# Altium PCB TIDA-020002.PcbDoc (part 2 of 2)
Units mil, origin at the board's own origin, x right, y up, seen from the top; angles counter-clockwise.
Board outline 1055.12 x 1877.5 mil, 6 copper layers (Layer 1 - Top Layer, Layer 2 - GND, Layer 3 - PWR, Layer 4 - Signal, Layer 5 - Signal/Gnd, Layer 6 - Bottom Layer), stack 62.2 mil thick; 103 components, 53 nets, 368 pads, 137 vias.
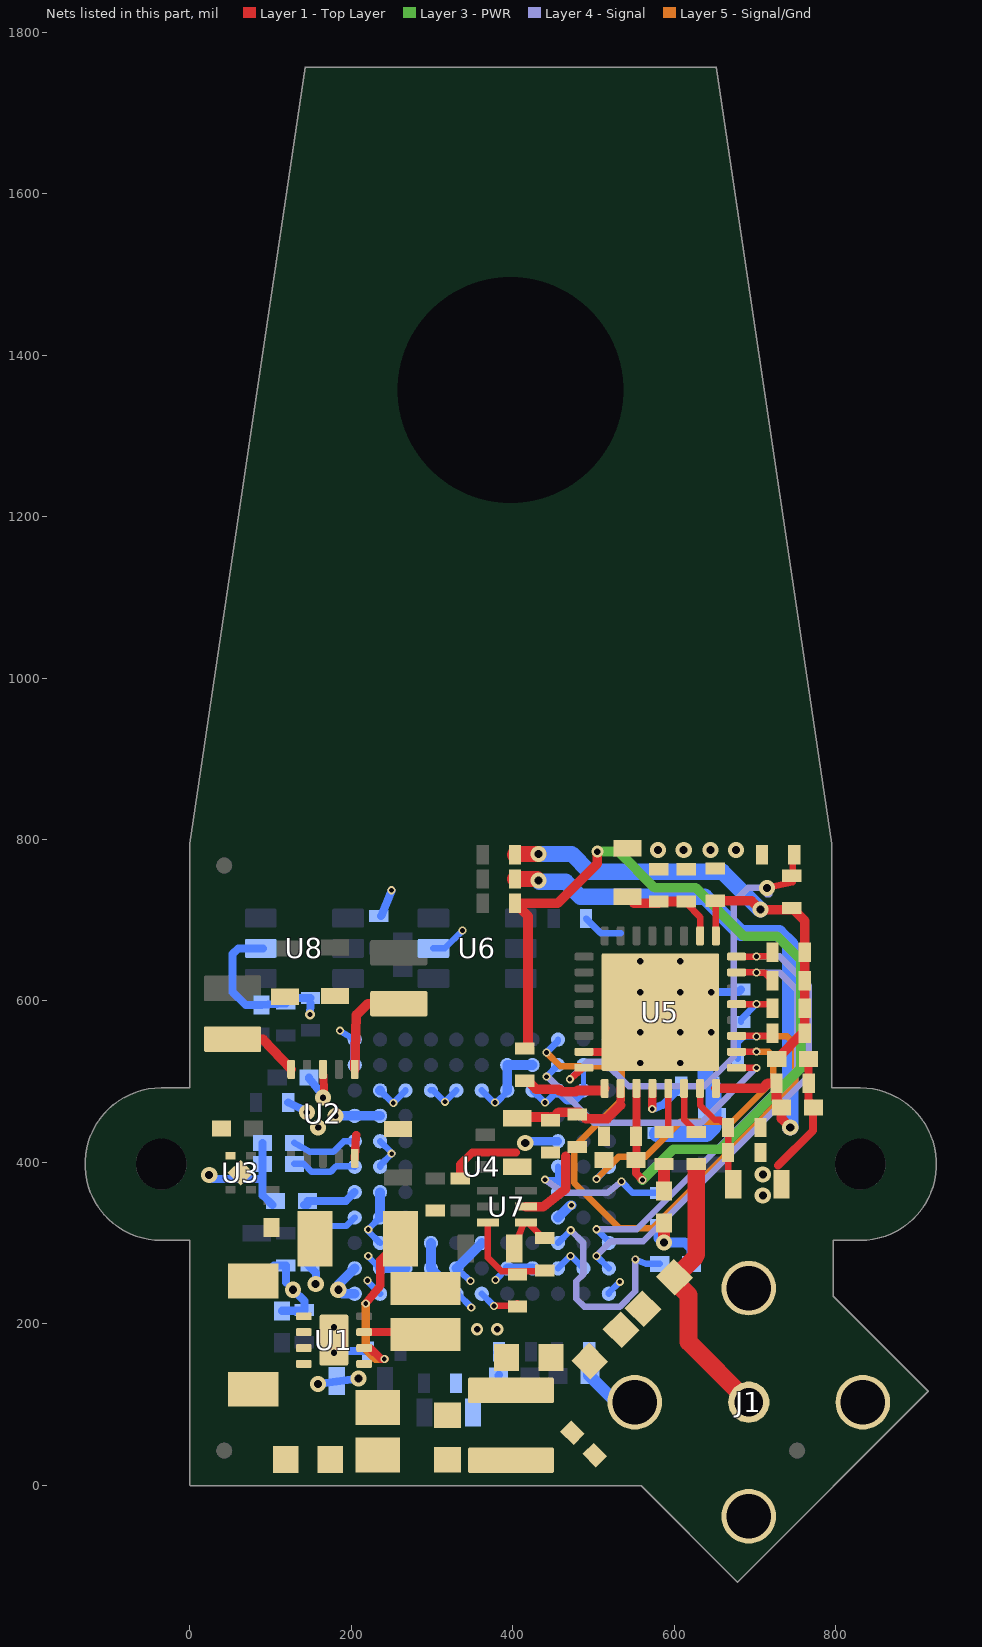
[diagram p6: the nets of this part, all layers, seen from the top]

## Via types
v1: diameter 10, hole 6, Layer 1 - Top Layer to Layer 6 - Bottom Layer, tented both sides, 88 vias
v2: diameter 20, hole 10, Layer 1 - Top Layer to Layer 6 - Bottom Layer, tented both sides, 26 vias
v3: diameter 19.68, hole 7.87, Layer 1 - Top Layer to Layer 6 - Bottom Layer, 10 vias
v4: diameter 19.68, hole 7.87, Layer 1 - Top Layer to Layer 6 - Bottom Layer, tented both sides, 6 vias
v5: diameter 15, hole 8, Layer 1 - Top Layer to Layer 6 - Bottom Layer, tented both sides, 6 vias
v6: diameter 12, hole 6, Layer 1 - Top Layer to Layer 6 - Bottom Layer, tented both sides, 1 vias

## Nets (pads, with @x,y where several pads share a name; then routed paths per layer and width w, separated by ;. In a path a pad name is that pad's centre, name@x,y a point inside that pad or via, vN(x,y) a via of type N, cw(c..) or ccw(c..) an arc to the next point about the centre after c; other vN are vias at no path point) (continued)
DOUTP_F: C40.1 J1.1 L2.1 | length 336.9
  Layer 1 - Top Layer w22: L2.1@598.44,255 625.64,281.64 ; L2.1@598.86,254.58 617.87,235.56 617.87,177.4 J1.1@692.64,102.64 ; 627.64,285.64 C40.1@627.64,393.64
FSIN: U4.L6 U5.18 | length 369.3
  Layer 1 - Top Layer w8: U5.18@677.49,536.79 v1@701.79,536.79
  Layer 5 - Signal/Gnd w8: v1(503.73,379) 531.73,407 565,407 608,450 672,450 723,501 723,531.29 717.29,537 v1(702,537)
  Layer 6 - Bottom Layer w8: v1@504,379.26 U4.L6@519.23,394.49
GND: C1.2 C2.2 C3.2 C4.2 C5.2 C6.2 C7.2 C8.2 C9.2 C10.2 C11.2 C12.2 C13.2 C14.2 C15.2 C16.2 C17.2 C18.2 C19.2 C20.2 C21.2 C22.2 C23.2 C24.2 C25.2 C26.2 C27.2 C28.2 C29.2 C30.2 C31.2 C32.2 C33.2 C34.2 C35.2 C36.2 C37.2 C38.2 C39.2 C41.2 C42.2 C44.2 C45.1 C46.2 C47.2 C48.1 C49.2 C50.2 C52.2 C53.1 C54.2 C55.2 C56.2 C57.2 C58.2 J1.2 J1.3 J1.4 J1.5 R11.1 R14.1 R15.1 R20.1 U1.1 U1.4 U1.5 U1.9 U2.5 U2.8 U3.2 U3.5 U4.A1 U4.A2 U4.A4 U4.A10 U4.A11 U4.B3 U4.B4 U4.B5 U4.B6 U4.B7 U4.B8 U4.B9 U4.B10 U4.B11 U4.C3 U4.C10 U4.D3 U4.D9 U4.D10 U4.E3 U4.E10 U4.E11 U4.F3 U4.F9 U4.F11 U4.G2 U4.G3 U4.G10 U4.H2 U4.H3 U4.H10 U4.J3 U4.J5 U4.J8 U4.J10 U4.K2 U4.K3 U4.K10 U4.L1 U4.L11 U5.7 U5.33@583,586 U6.2 U7.5 U8.2 | length 2773.5
  Layer 1 - Top Layer w8: v1(376.74,222) 403,222 R20.1@406,225
  Layer 1 - Top Layer w10: U2.8@165,515.12 v4@167,480 ; U2.5@204.37,404.88 206,434 206.37,433.63 ; C58.2@335,380 335,397 350,412 404,412 ; U5.7@488.51,536.79 533.79,536.79 U5.33@583,586 ; 729,396 772.45,439.45 772.45,470.97 766.69,476.73 C36.2@766.69,528
  Layer 1 - Top Layer w12: U7.5@416.62,345 438,345 466,367 466,407
  Layer 1 - Top Layer w15: v2@587.64,302.64 R11.1@587.64,324.95 R11.1@587.64,327.95
  Layer 6 - Bottom Layer w6: U4.K3@487.73,488.98 U4.K2@487.73,520.47
  Layer 6 - Bottom Layer w8: v1(186,563) U4.A1@204.27,551.97 ; U4.A1@201.92,554.31 U4.A1@205.69,554.31 ; v1@220.77,252 U4.B11@235.76,237.01 ; v1@221.14,314.62 U4.B9@235.76,300 ; v1@221.27,283 U4.B10@235.76,268.5 ; v1@221.27,317 U4.B8@235.76,331.5 ; U4.B6@235.76,394.49 235.76,396.02 250.75,411 U4.B5@235.76,425.98 ; U4.B3@235.76,488.98 251.74,473 267.26,488.52 U4.C3@267.26,488.98 ; U4.D3@298.76,488.98 301.75,488.98 316,474.72 U4.E3@330.25,488.98 ; U6.2@301.87,665 315.97,665 v1(337.91,686.94) ; U4.E11@330.25,237.01 331.99,237.01 v1@349,220 ; U4.E10@330.25,268.5 v1(348,253) ; U4.F11@361.75,237.01 v1@375.76,223 ; U4.F3@361.75,488.98 376.72,474 380,474 393.24,487.24 U4.G3@393.24,488.98 ; v1(378.74,254) U4.G10@393.24,268.5 ; U4.H3@424.74,488.98 v1@439.72,474 ; v1@441.26,474 U4.J3@456.24,488.98 ; U4.J10@456.24,268.5 471.73,284 472.24,284 U4.K10@487.73,268.5 ; C56.2@491,702 509,684 534,684 ; U4.L11@519.23,237.01 519.23,238.23 v1@532,251
  Layer 6 - Bottom Layer w10: v2@29,379 90.31,379 ; C14.2@86,252 86,253.5 104.5,272 C15.2@119,272 119,251 ; C28.2@90.31,424 C29.2@90.31,398 90.31,379 ; U8.2@90.87,665 60,665 53,658 53,611 69.31,594.69 C25.2@89,594.69 C26.2@119,597 125.5,603.5 C27.2@149.5,603.5 ; C30.2@102.31,347 90.31,359 90.31,379 ; C18.2@114,215.69 114,216 141,216 C19.2@142,217 142,228 v2(128,242) ; C11.2@122,474 v4@147,462 ; C35.2@147,272 156.27,262.73 v2@156.27,249.27 ; C10.2@147.69,505 147.69,503.92 v4@167,480 ; v6@149.5,583.5 v6(149,583) C27.2@149.5,597 ; v2(159,125) v2(209,132) ; v4@180.75,166 C17.2@221,166 ; C57.2@237,705 v1(250,737) ; C12.2@382.31,136 C12.2@383,136.69 ; v2@417.98,425.98 U4.J5@456.24,425.98 ; v3(645.99,610.8) 679.8,610.8 R15.1@683,614
  Layer 6 - Bottom Layer w12: v4@182.52,457.48 U4.A4@204.27,457.48 U4.B4@235.76,457.48 ; v2(184,242) v2@188.99,242 ; v2@184,248.24 U4.A10@204.27,268.5 ; v2@188.99,237.01 U4.A11@204.27,237.01 ; U4.A2@204.27,520.47 U4.A1@204.27,551.97 ; U4.B10@235.76,268.5 U4.C10@267.26,268.5 ; U4.B8@235.76,331.5 U4.B7@235.76,362.99 ; U4.D9@298.76,300 U4.D10@298.76,268.5 U4.E11@330.25,237.01 ; U4.E10@330.25,268.5 U4.F9@361.75,300 ; C13.2@382.31,164.31 C13.2@383,165 ; U4.G10@393.24,268.5 U4.H10@424.74,268.5 ; U4.G3@393.24,488.98 U4.G2@393.24,520.47 U4.H2@424.74,520.47 ; v2(415.64,423.64) v2@417.98,425.98 ; U4.J8@456.24,331.5 471.47,346.73 v1(473.13,346.73) ; U4.J3@456.24,488.98 467.59,477.62 476.37,477.62 U4.K3@487.73,488.98 ; v2(587.64,300.64) 613.36,300.64 621.69,292.31 C34.2@621.69,274
  Layer 6 - Bottom Layer w15: C32.2@495,165 495,135.69 C31.2@495.69,135 J1.3@528.05,102.64 ; v2@582,306.28 C33.2@582,322
  Layer 6 - Bottom Layer w20: C24.2@579,435 C23.2@609,435 640,435 649,444 C55.2@649,494 639,506 R14.1@639,528 v3@639,564
  other v1: 348.74,220 532.81,251.81 220.14,253.61 221.14,283.61 471.81,283.81 221.14,316.61 250.14,410.61 252.14,473.61 378.24,473.87 440,474 316.24,474.87
  other v2: 156,249 710,359 24,384 710,385 580,787 612,787 645,787 677,787
  other v3: 558.2,523.01 607.8,523.01 558.2,561.2 607.8,561.2 645.99,561.2 558.2,610.8 607.8,610.8 558.2,648.99 607.8,648.99
  other v4: 178.64,163.89 178.64,195.39 159,443 180.52,457.48 145,462 165,480
  other v5: 356,193 381,193
NetC1_1: C1.1 C2.1 L5.1 L6.1 R1.1
NetC4_1: C4.1 L1.2 R2.2 U1.6 | length 239.1
  Layer 1 - Top Layer w10: U1.6@216.04,169.8 223.46,169.8 237.26,156 v1(241,156) ; v1(218,225) 236,247 236,278.85 C4.1@260.15,303 ; C4.1@261.15,304 C4.1@260.15,303 ; C4.1@266.15,303 C4.1@260.15,303 ; L1.2@272.46,237 L1.2@287.64,252.18
  Layer 5 - Signal/Gnd w10: v1(218,225) 218,167.83 229.83,156 v1(241,156)
NetC28_1: C28.1 U4.A5 | length 82.9
  Layer 6 - Bottom Layer w8: C28.1@129.69,424 148.69,413 178,413 190.98,425.98 U4.A5@204.27,425.98
NetC29_1: C29.1 U4.A6 | length 81.8
  Layer 6 - Bottom Layer w8: C29.1@129.69,398 141,398 151,388 174.2,388 181.2,395 203.76,395 U4.A6@204.27,394.49
NetC30_1: C30.1 U4.A7 | length 67.1
  Layer 6 - Bottom Layer w10: C30.1@141.69,347 C30.1@145.69,347 ; C30.1@145.69,352 193.28,352 U4.A7@204.27,362.99
NetC33_1: C33.1 U4.J6 U4.J7 | length 204.5
  Layer 4 - Signal w8: v1(440.15,378.39) 463,362 517.19,362 v1(535,376)
  Layer 6 - Bottom Layer w8: v1@441,378 456.24,378 ; U4.J7@456.24,362.99 456.24,378 ; U4.J6@456.24,394.49 456.24,378 ; v1(535,376) 549,362 C33.1@582,362
NetC34_1: C34.1 U4.J9 | length 272.2
  Layer 4 - Signal w8: v1(472,315.71) 487.73,299.97 487.73,261.27 479,252.54 479,231 489,221 533,221 552,240 v1(552,279.71)
  Layer 6 - Bottom Layer w8: U4.J9@456.24,300 v1@471.24,315 ; v1(552,279.71) 566,274 C34.1@582.31,274
NetC35_1: C35.1 U4.A8 | length 65.6
  Layer 6 - Bottom Layer w8: C35.1@147,312 156.27,321.27 156.54,321 193.77,321 U4.A8@204.27,331.5
NetC40_2: C40.2 U5.14 | length 63.1
  Layer 1 - Top Layer w8: U5.14@612.53,491.51 612.53,452.75 C40.2@627.64,437.64 C40.2@624.64,437.64
NetC43_1: C43.1 R11.2 | length 30.3
  Layer 1 - Top Layer w15: R11.2@587.64,367.32 C43.1@587.64,397.64
NetC43_2: C43.2 U5.13 | length 56
  Layer 1 - Top Layer w8: C43.2@587.64,437.64 592.84,442.84 U5.13@592.84,491.51
NetC50_1: C50.1 R10.1 U5.8 | length 572.9
  Layer 1 - Top Layer w8: v1(470.85,502.87) U5.8@488.51,517.1 ; v2(715,740) 747,747 747,779 C50.1@749,781
  Layer 4 - Signal w8: v1(470.85,502.87) 492.32,524.34 513.67,524.34 544,494 637.35,494 674,530.65 674,722 692,740 v2(715,740) ; v2@715,732 v2@718,732
NetC51_2: C51.2 U5.9 | length 101.7
  Layer 1 - Top Layer w12: C51.2@419,500.47 429,490.47 457.53,490.47 ; 457.53,489 459,489 460.75,487.25 479.03,487.25 480.78,489 511.59,489 U5.9@514.1,491.51
NetC55_1: C55.1 U5.12 | length 72
  Layer 1 - Top Layer w10: v1(573,466) U5.12@573.16,491.51
  Layer 6 - Bottom Layer w10: v1(573,466) 586,471 C55.1@609,494
NetL1_1: L1.1 U1.7 | length 73.9
  Layer 1 - Top Layer w10: U1.7@216.04,189.48 282.02,189.48 L1.1@287.64,195.09
NetL2_2: L2.2 L3.1
NetL3_2: L3.2 L4.1
NetL4_2: L4.2 L5.2 R1.2
NetL7_1: L7.1 U2.6 | length 125.8
  Layer 1 - Top Layer w12: U2.6@204.37,515.12 206.37,582.37 220.5,596.5 L7.1@259,596.5
NetL8_1: L8.1 U2.10 | length 89.2
  Layer 1 - Top Layer w12: L8.1@53,552.5 91.09,552.5 91.09,551.66 U2.10@125.63,515.12
NetR13_1: R13.1 R15.2 U5.21 | length 76.5
  Layer 1 - Top Layer w8: U5.21@677.49,595.84 701.84,595.84 v1(702,596) 717,596 R13.1@722,591
  Layer 6 - Bottom Layer w8: R15.2@683,574 683,577 v1(702,596)
NetR17_1: R17.1 R19.2 U7.4 | length 67.4
  Layer 1 - Top Layer w8: R17.1@402,294 412,320.69 U7.4@416.62,325.32 418.88,325.32 R19.2@440.2,304
NetR19_1: R19.1 R20.2 U7.3 | length 118.5
  Layer 1 - Top Layer w8: U7.3@369.38,325.32 369.38,281.75 386.12,265 406,265 436,265 R19.1@437,266
SCL: R8.1 U4.L10 U5.24 | length 615.4
  Layer 1 - Top Layer w8: U5.24@677.49,654.9 v1@701.9,654.9 ; v1(702,655) 717,655 R8.1@722,660
  Layer 4 - Signal w8: v1(504,284) 522,302 561.69,302 767,507.31 767,619 731,655 v1(702,655)
  Layer 6 - Bottom Layer w8: v1(504,284) 504,283.73 U4.L10@519.23,268.5
SDA: R9.1 U4.L9 U5.23 | length 557
  Layer 1 - Top Layer w8: U5.23@677.49,635.21 v1@701.79,635.21 ; v1(702,635) 712,635 R9.1@722,625
  Layer 4 - Signal w8: v1(504,317) 553.84,317 752.73,515.89 ; v1(702,635) 730.81,635 752.73,613.09 752.73,518.7
  Layer 6 - Bottom Layer w8: v1(504,317) 519.23,301.77 U4.L9@519.23,300
SYS_CLEAR: U4.J2 U5.17 | length 356.3
  Layer 1 - Top Layer w8: U5.17@677.49,517.1 v1@701.9,517.1
  Layer 4 - Signal w8: v1@442.58,506.99 500.57,449 634,449 v1(702,517)
  Layer 6 - Bottom Layer w8: v1(442,506) U4.J2@456.24,520.47
VCC_PLL: C38.1 C39.1 C51.1 L10.2 U5.11 | length 1137.3
  Layer 1 - Top Layer w10: U5.11@553.47,491.51 553.47,403.79 C38.1@552.69,403 552.69,386.32 v1(561,378)
  Layer 1 - Top Layer w12: C51.1@419,540.47 419,705 L10.2@403,721 456,721 505,770 v5(505,785)
  Layer 3 - PWR w12: v5(505,785) 531,785 576,740 627,740 687,680 728,680 756.93,651.07 756.93,515.93 657,416 599,416 v1(561,378)
VCC_POC: C3.1 L6.2 U1.2 U1.3
VDD1: C36.1 C37.1 L9.2 R8.2 R9.2 R10.2 R12.2 R13.2 U5.25 | length 679.1
  Layer 1 - Top Layer w8: C37.1@651,721 651.9,720.1 U5.25@651.9,680.49
  Layer 1 - Top Layer w12: C37.1@651,724 696,724 v2(707,713) 744,713 R10.2@746,715 762,699 R8.2@762,660 ; C36.1@727.31,528 759.31,560 R12.2@762,560 R13.2@762,591 R9.2@762,625 R8.2@762,655.28
  Layer 1 - Top Layer w20: L9.2@403,781 404,782 v2(432,782)
  Layer 6 - Bottom Layer w20: v2(432,782) 473,782 495,760 660,760 v2(707,713)
VDD1_CAP: C44.1 C45.2 C46.1 U5.26 | length 124.4
  Layer 1 - Top Layer w8: C44.1@581,721 C44.1@583,723 ; C46.1@615,721 632.21,703.79 U5.26@632.21,680.49
  Layer 1 - Top Layer w12: C45.2@542.39,729 550.39,721 C44.1@581,721 ; C44.1@583,723 C46.1@615,723
VDDDRV: C41.1 C42.1 L11.2 U5.16 | length 738.7
  Layer 1 - Top Layer w12: U5.16@651.9,491.51 709.51,491.51 716,498 C42.1@727,498 727,477.05 733.08,470.97 733.08,453.92 v2(744,443)
  Layer 1 - Top Layer w20: L11.2@403,751 v2@430,751
  Layer 6 - Bottom Layer w20: v2(432,749) 433.5,747.5 465.8,747.5 474,739.3 474,739 484,729 638,729 683,684 730,684 744,670 v2(744,443)
VDDDRV_CAP: C47.1 C48.2 C49.1 U5.15 | length 140
  Layer 1 - Top Layer w8: U5.15@632.21,491.51 632.21,470.79 650.5,452.5 657.5,452.5 C49.1@667,443 C47.1@667,412 667,379.02 C48.2@673.39,372.64
VDDPLL_CAP: C52.1 C53.2 C54.1 U5.10 | length 156.9
  Layer 1 - Top Layer w10: 533.79,470.79 U5.10@533.79,491.51
  Layer 1 - Top Layer w12: C53.2@412,456 C52.1@444,456 ; C52.1@447,452 C52.1@451,456 ; C52.1@448,456 C52.1@451,456 ; 533.79,470.79 517,454 491,454 483,462 468.5,462 457,462 C52.1@451,456
XCLK: R12.1 R14.2 U4.J1 U5.19 | length 852.5
  Layer 1 - Top Layer w8: U5.19@677.49,556.47 718.47,556.47 R12.1@722,560
  Layer 5 - Signal/Gnd w8: v1(442,536) 459,519 528,519 535.05,511.95 535.05,477.68 476.36,419 476.36,374.36 532.72,318 573,318 750,495 750,546 740,556 v1(702,556)
  Layer 6 - Bottom Layer w8: v1(442,536) 456.24,550.24 U4.J1@456.24,551.97 ; R14.2@679,528 679,548 687,556 v1(702,556)
pads on no net: FID1.1 FID2.1 FID3.1 FID4.1 FID5.1 FID6.1 LH1.MT1 LH1.MT2 U1.8 U2.11 U4.A9 U4.F10 U4.G11 U4.K4 U4.K5 U4.K6 U4.K7 U4.K8 U4.K9 U4.L5 U4.L8 U5.20 U5.22 U5.33@533.39,536.39 U5.33@533.39,586 U5.33@533.39,635.61 U5.33@583,536.39 U5.33@583,586 U5.33@583,635.61 U5.33@632.61,536.39 U5.33@632.61,586 U5.33@632.61,635.61

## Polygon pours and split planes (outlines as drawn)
GND on Layer 2 - GND "Layer 2 - GND - GND" (solid, remove dead copper, pour order 16): 677.64,-142.36 -132.36,-142.36 -132.36,799.64 917.64,799.64 917.64,-142.36
GND on Layer 3 - PWR "Layer 5 - PWR - GND" (solid, remove dead copper, pour order 10): 677.64,-142.36 -132.36,-142.36 -132.36,799.64 917.64,799.64 917.64,-142.36
GND on Layer 4 - Signal "Layer 4 - Signal - GND" (solid, remove dead copper, pour order 14): 677.35,-141.09 -132.65,-141.09 -132.65,800.91 917.35,800.91 917.35,-141.09
GND on Layer 5 - Signal/Gnd "Layer 3 - Signal - GND" (solid, remove dead copper, pour order 12): 677.64,-142.36 -132.36,-142.36 -132.36,799.64 917.64,799.64 917.64,-142.36
1V8 on Layer 1 - Top Layer "1V8_L01_P018" (solid, remove dead copper, pour order 18): 20,678 20,796.99 19.99,797 371,797 371,709 372,708 366.4,702.4 301.87,702.4 301.87,731.13 301,732 137,732 137,670 135,672 20,672 20,678

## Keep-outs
Keep-Out Layer:
  lines w10: -35.48,298.15 ccw(c-35.43,303.15) -35.43,298.15 ; -35.48,298.15 cw(c-35.43,397.64) -35.48,497.13 ; -35.48,298.15 ccw(c-35.43,397.64) -35.43,298.15 ; -35.48,497.13 cw(c-35.43,397.64) -35.43,497.13 ; -35.48,497.13 cw(c-35.43,492.13) -35.43,497.13 ; -35.48,497.13 cw(c-35.43,492.13) -35.43,497.13 ; -35.43,298.15 -5,298.15 -5,0 ; -35.43,497.13 -5,497.13 -5,794.57 ; -5,0 ccw(c0,0) -3.54,-3.54 -3.52,-3.55 ; -5,0 ccw(c0,0) -3.52,-3.55 ; -5,794.57 cw(c0,794.64) -5,794.64 ; -5,794.57 cw(c0,794.64) -5,794.64 ; -5,794.57 -5,794.71 ; -5,794.64 cw(c0,794.64) -5,794.71 ; -5,794.64 -5,795.28 ; -5,794.71 -5,795.28 ; -5,795.28 cw(c0,795.28) -4.71,796.95 ; -5,795.28 ccw(c0,795.28) -5,795.28 ; -5,795.28 cw(c0,795.28) -4.71,796.95 ; -4.71,796.95 137.94,1757.87 ; -3.52,-3.55 -2.56,-4.51 ; -2.56,-4.51 ccw(c0.99,-0.99) 0.99,-5.99 ; -2.54,-4.53 ccw(c0.99,-0.99) 0.99,-5.99 ; -2.56,-4.51 -2.54,-4.53 ; 0.99,-5.99 557.2,-5.99 675.08,-123.88 ; 137.94,1757.87 cw(c142.89,1757.14) 142.89,1762.14 ; 137.94,1757.87 cw(c142.89,1757.14) 142.89,1762.14 ; 142.89,1762.14 652.39,1762.14 ; 652.39,1762.14 cw(c652.39,1757.14) 657.33,1757.87 ; 652.39,1762.14 cw(c652.39,1757.14) 657.33,1757.87 ; 657.33,1757.87 799.99,796.95 ; 675.08,-123.88 ccw(c678.64,-120.36) 682.17,-123.9 682.19,-123.88 ; 675.08,-123.88 675.1,-123.9 ccw(c678.64,-120.36) 682.19,-123.88 ; 682.19,-123.88 918.66,112.58 ; 799.99,796.95 cw(c795.28,795.28) 800.28,795.28 ; 799.99,796.95 cw(c795.28,795.28) 800.28,795.28 ; 800.28,794.55 ccw(c795.28,794.64) 800.28,794.64 ; 800.28,794.55 ccw(c795.28,794.64) 800.28,794.64 ; 800.28,794.55 800.28,497.13 830.71,497.13 ; 800.28,794.55 800.28,794.73 ; 800.28,794.64 ccw(c795.28,794.64) 800.28,794.64 ; 800.28,794.64 ccw(c795.28,794.64) 800.28,794.64 ; 800.28,794.64 ccw(c795.28,794.64) 800.28,794.73 ; 800.28,794.64 800.28,795.28 ; 800.28,794.73 800.28,795.28 ; 800.28,795.28 ccw(c795.28,795.28) 800.28,795.28 ; 830.71,298.15 ccw(c830.71,303.15) 830.71,298.15 ; 830.71,298.15 ccw(c830.71,303.15) 830.75,298.15 ; 830.71,298.15 ccw(c830.71,303.15) 830.75,298.15 ; 830.71,298.15 ccw(c830.71,397.64) 830.75,298.15 ; 830.71,298.15 802.27,298.15 802.27,236.08 918.66,119.69 ; 830.71,497.13 cw(c830.71,492.13) 830.75,497.13 ; 830.71,497.13 ccw(c830.71,492.13) 830.71,497.13 ; 830.71,497.13 cw(c830.71,397.64) 830.75,497.13 ; 830.71,497.13 cw(c830.71,492.13) 830.75,497.13 ; 830.75,298.15 ccw(c830.71,397.64) 930.2,397.64 ccw(c830.71,397.64) 830.75,497.13 ; 918.66,112.58 ccw(c915.14,116.14) 920.14,116.14 ; 918.66,112.58 918.67,112.6 ccw(c915.14,116.14) 920.14,116.14 ; 918.66,119.69 cw(c915.14,116.14) 920.14,116.14 ; 918.66,119.69 918.67,119.67 cw(c915.14,116.14) 920.14,116.14
  text ".Layer_Name" at 444.64,-860.86 h60

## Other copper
Layer 1 - Top Layer:
  region net NetC4_1: 269,336 280,336 291,347 315,347 315,330 312,330 289,330 289,328 289,266.82 335.12,266.82 334.88,223 244.64,223 244.64,336
  region net GND: 570,750 561,759 523.78,759 522.64,760.14 522.64,799 717,799 717,758.64 708.64,758.64 700.64,752.27 700.64,750
  region net GND: 699,450 699,347.64 743.64,347.64 743.64,391.64 717,418.28 717,455.64 704.64,455.64
  region net NetL2_2: 505.14,189.14 530.64,163.64 581.14,214.14 555.64,239.64
  region net GND: 483.64,37.64 512.64,66.64 512.64,106.64 512.64,118.64 533.64,139.64 565.64,139.64 591.64,113.64 591.64,87.64 562.64,58.64 552.76,58.64 507.2,13.08 483.64,36.64
  region net GND: 128.37,315.37 149,336 196,336 195.91,279.64 196.64,192.64 196.92,158.27 196.92,154 224.64,154 224.64,142.63 247.63,119.64 262.64,119.64 262.64,74.64 159.64,74.64 159.64,108.08 132,138.89 132,154 152.49,154 159.64,158.55 159.64,204 59.28,204 45,218.27 45,321 45,330 103.35,330 117.98,315.37
  region net NetC1_1: 436.64,45.64 442,51 472,81 490,63 457,30 457,14.64 157.64,14.64 157.64,49.64 169.64,49.64 178.64,58.64 259.64,58.64 272.64,45.64
  region net VCC_POC: 135.64,69.64 112.64,92.64 112.64,159.27 119.01,165.64 151.64,165.64 151.64,193.64 150.64,194.64 109.64,194.64 44,129 44,95.64 54.64,95.64 101.64,48.64 102.64,48.64 102.64,13.64 103.64,14.64 135.64,14.64
  region net NetL3_2: 434,173 434,143 433,142 478,142 493,127 515,149 491,173
  region net NetL4_2: 378,143 368,133 333,133 304,104 304,74 337,74 366,103 451,103 450,104 450,133 420,133 409,144 409,175 379,175 378,175
  region net 3V3: 226,349 249,372 316,372 316,386 231,386 215,370 177,370 172,375 172,417 141,417 142.93,368.08 69.35,367.69 67.4,365.74 59.26,365.74 56,369 43.46,369 43.46,349
  region net 1V8: 138,678 138,651 84,651 84,601 20,601 20,678
  region net 1V2: 295,725 160.42,725 142.89,725 142.89,682 160.42,682 160.42,642.5 295,642.5
  region net GND: 56,381 63,374 67,374 78.5,385.5 56.27,407.73 56.27,452.16 27.16,452.16 27,396 17,386 17,381 18,376 21.77,372.23 24,372 29,372 38,381
  region net GND: 491,428 506,443 507,442 524,442 524,390 395,390 395,428
  region net GND: 132,594.69 160,559.51 160,514 171,514 172,557 194,557 194,576.5 194,615.85 102,615.85 102,594.68
  text ".Layer_Name" at 444.64,-860.86 h60
Layer 2 - GND:
  pour cut-out: 336,15 335,16 335,144 468,144 467,143 467,16 338,16 336,14
  text ".Layer_Name" at 444.64,-860.86 h60
Layer 3 - PWR:
  region net 1V2: 15.39,402.8 34.2,402.8 42,395 42,375.07 15.39,353.97 15.39,12 110.91,12 491,12 494,15 494,119 257,119 257,82 65,82 65,680.51 179.06,680.51 179.06,725 15.39,725 15.39,573.61
  region net 2V9: 96,90 96,521 70.27,521 70.27,90
  text ".Layer_Name" at 444.64,-860.86 h60
Layer 5 - Signal/Gnd:
  text ".Layer_Name" at 444.64,-860.86 h60
Layer 4 - Signal:
  text ".Layer_Name" at 444.64,-860.86 h60
Layer 6 - Bottom Layer:
  region net GND: 524,687 524,578.05 511,559 511,544 659,544 659,618 590,687
  region net GND: 394.5,206 394.5,75 324,75 324,206
  text ".Layer_Name" at 444.64,-860.86 h60

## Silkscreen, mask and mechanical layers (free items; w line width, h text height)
Top Overlay:
  text "TIDA-020002" at 223,552 h40
  text ".Layer_Name" at 444.64,-860.86 h60
Bottom Overlay:
  lines w6: 165.9,553 165.9,565.9
  lines w10: 61.64,732.64 63,332 ; 62.64,732.64 732.64,732.64 732.64,62.64 62.64,62.64 63,234
  text ".Layer_Name" at 444.64,-860.86 h60
Top Paste:
  text ".Layer_Name" at 444.64,-860.86 h60
Bottom Paste:
  text ".Layer_Name" at 444.64,-860.86 h60
Top Solder:
  text ".Layer_Name" at 444.64,-860.86 h60
  text ".Layer_Name" at 444.64,-860.86 h60
Bottom Solder:
  text ".Layer_Name" at 444.64,-860.86 h60
Drill Guide:
  text ".Layer_Name" at 444.64,-860.86 h60
M1 Board Outline:
  lines w10: 0,0 0,303.15 -35.43,303.15 cw(c-35.43,397.64) -35.43,492.13 0,492.13 0,795.28 ; 0,794.64 142.89,1757.14 652.39,1757.14 795.28,794.64 ; 0.99,-0.99 559.27,-0.99 678.64,-120.36 915.14,116.14 797.27,234.01 797.27,303.15 830.71,303.15 ccw(c830.71,397.64) 830.71,492.13 795.28,492.13 795.28,795.28 ; 4.64,819.64 31.64,819.64 ; 63.64,819.64 95.28,819.64 ; 127.28,819.64 158.91,819.64 ; 190.91,819.64 222.55,819.64 ; 254.55,819.64 286.19,819.64 ; 318.19,819.64 349.83,819.64 ; 381.83,819.64 413.46,819.64 ; 387.64,780.64 404.64,780.64 ; 397.64,732.64 397.64,772.64 ; 445.46,819.64 477.1,819.64 ; 509.1,819.64 540.74,819.64 ; 572.74,819.64 604.38,819.64 ; 636.38,819.64 668.02,819.64 ; 700.02,819.64 731.65,819.64 ; 763.65,819.64 790.64,819.64 ; 377.64,772.64 417.64,772.64 397.64,792.64 377.64,772.64
  text "V-SCORE" at 237.64,663.64 h75
  text ".Layer_Name" at 444.64,-860.86 h60
M2 Board Dimensions:
  rectangle: -7.86,-412.86 367.14,-287.86
  rectangle: -132.86,-287.86 -7.86,-162.86
  lines w7: -132.86,-287.86 867.14,-287.86 ; -7.86,-412.86 -7.86,-162.86 ; 117.14,-412.86 117.14,-162.86 ; 367.14,-412.86 367.14,-162.86 ; 617.14,-412.86 617.14,-162.86 ; -132.86,-412.86 -132.86,-162.86 867.14,-162.86 867.14,-412.86 -132.86,-412.86
  lines w10: -172.36,397.64 397.64,397.64 ; -132.86,-477.86 -132.86,-457.86 ; -72.86,-487.86 -132.86,-467.86 ; -72.86,-447.86 -132.86,-467.86 ; 91.22,-467.86 -132.86,-467.86 ; 397.64,-172.36 397.64,397.64 ; 397.64,967.64 397.64,397.64 ; 643.05,-467.86 867.14,-467.86 ; 807.14,-487.86 867.14,-467.86 ; 807.14,-447.86 867.14,-467.86 ; 867.14,-477.86 867.14,-457.86 ; 967.64,397.64 397.64,397.64
  text "1000 (mil)" at 101.22,-503.85 h60
  text ".Layer_Name" at 444.64,-860.86 h60
M3 3D STEP Top:
  text ".Layer_Name" at 444.64,-860.86 h60
M4 3D STEP Bottom:
  text ".Layer_Name" at 444.64,-860.86 h60
M5 Assembly Top:
  lines w10: -424.36,-932.53 6175.64,-932.53 ; -424.36,-729.2 6177.64,-729.2 ; -424.36,-525.86 -424.36,-1135.86 3580.64,-1135.86 6177.64,-1135.86 6177.64,-525.86 -423.86,-525.86 -423.86,-1135.86 1151.64,-1135.86 ; 2040.64,-1135.86 2040.64,-525.86 ; 3307.64,-729.2 3307.64,-525.86 ; 4147.64,-729.2 4147.64,-525.86 ; 4769.64,-1142.36 4769.64,-939.53
  text "COMPONENTS MARKED 'DNP' SHOULD NOT BE POPULATED." at 1021.14,-320.86 h60
  text "ASSEMBLY VARIANT:" at 1020.64,-436.36 h60
  text ".VariantName" at 2056.64,-436.36 h60
  text "PCB VIEWED FROM TOP SIDE" at -360.86,-658.03 h60
  text "BOARD #:" at 2115.64,-658.03 h60
  text ".PRJ_Number" at 2661.14,-658.03 h60
  text "REV:" at 3505.64,-658.03 h60
  text ".PCB_Rev" at 3797.14,-658.03 h60
  text "SVN REV:" at 4343.64,-658.03 h60
  text ".VersionControl_RevNumber" at 4849.64,-658.03 h60
  text "IGNORE ->" at -360.86,-860.86 h60
  text "PLOT NAME =" at -360.86,-1066.7 h60
  text ".plot_File_Name" at 444.64,-1066.7 h60
  text "GENERATED    :" at 2117.64,-1066.7 h60
  text ".Print_Date" at 2987.14,-1066.7 h60
  text ".Print_Time" at 3716.14,-1066.7 h60
  text "TEXAS INSTRUMENTS" at 4980.64,-1066.7 h60
M6 Assembly Bottom:
  lines w10: -424.86,-729.7 6177.14,-729.7 ; -422.86,-933.03 6177.14,-933.03 ; 983.14,-1142.86 983.14,-940.03 ; 1605.14,-729.7 1605.14,-526.36 ; 2445.14,-729.7 2445.14,-526.36 ; 3712.14,-1136.36 3712.14,-526.36 ; 4601.14,-1136.36 6176.64,-1136.36 6176.64,-526.36 -424.86,-526.36 -424.86,-1136.36 2172.14,-1136.36 6177.14,-1136.36 6177.14,-526.36
  text "COMPONENTS MARKED 'DNP' SHOULD NOT BE POPULATED." at 5969.64,-320.36 h60
  text ".VariantName" at 4925.64,-436.36 h60
  text "ASSEMBLY VARIANT:" at 5964.64,-436.36 h60
  text ".VersionControl_RevNumber" at 903.14,-658.53 h60
  text "SVN REV:" at 1409.14,-658.53 h60
  text ".PCB_Rev" at 1955.64,-658.53 h60
  text "REV:" at 2247.14,-658.53 h60
  text ".PRJ_Number" at 3091.64,-658.53 h60
  text "BOARD #:" at 3637.14,-658.53 h60
  text "PCB VIEWED FROM BOTTOM SIDE" at 6113.64,-658.53 h60
  text "IGNORE ->" at 2415.49,-860.86 h60
  text "TEXAS INSTRUMENTS" at 772.14,-1067.2 h60
  text ".Print_Time" at 2036.64,-1067.2 h60
  text ".Print_Date" at 2765.64,-1067.2 h60
  text "GENERATED    :" at 3635.14,-1067.2 h60
  text ".plot_File_Name" at 5308.14,-1067.2 h60
  text "PLOT NAME =" at 6113.64,-1067.2 h60
M9 Title Sheet:
  drawing of 1178 lines, arcs and shapes, not listed
  text "1" at 607.48,8034.14 h70
  text "2" at 3103.14,8034.14 h70
  text "3" at 5592.48,8034.14 h70
  text "4" at 8099.15,8034.14 h70
  text "5" at 10598.14,8034.14 h70
  text "6" at 13103.14,8034.14 h70
  text "A" at -548.86,6891.14 h70
  text "A" at 14251.14,6891.14 h70
  text "B" at -548.86,4511.14 h70
  text "B" at 14251.14,4511.14 h70
  text "C" at -548.86,2136.14 h70
  text "C" at 14251.14,2136.14 h70
  text "PROJECT TITLE:" at 11211.14,275.14 h45
  text ".PRJ_Title" at 11261.14,141.81 h70
  text "DESIGNED FOR:" at 11211.14,-25.86 h45
  text ".PRJ_Customer" at 11261.14,-165.86 h70
  text "D" at -548.86,-233.86 h70
  text "D" at 14251.14,-233.86 h70
  text "FILE NAME:" at 11211.14,-325.86 h45
  text ".PCB_File_Name_No_Path" at 11261.14,-445.86 h70
  text "Texas Instruments (TI) and/or its licensors do not warrant the accuracy or completeness of this specification" at 6241.64,-607.7 h45
  text "ENGINEER:" at 11211.14,-615.86 h45
  text "LAYOUT BY:" at 12716.14,-615.86 h45
  text "or any information contained therein. TI and/or its licensors do not warrant that this design will meet" at 6196.65,-720.37 h45
  text ".PRJ_Engineer" at 11261.14,-770.85 h70
  text "JMM" at 12719.64,-802.36 h100
  text "s  o  l  u  t  i  o  n  s" at 13577.64,-805.36 h68
  text "the specifications, will be suitable for your application or fit for any particular purpose, or will operate in" at 6196.65,-833.03 h45
  text ".Layer_Name" at 444.64,-860.86 h60
  text "ALTIUM DESIGNER VERSION:" at 12716.14,-925.86 h45
  text "an implementation. TI and/or its licensors do not warrant that the design is production worthy. You should" at 6196.65,-945.7 h45
  text "completely validate and test your design implementation to confirm the system functionality for your application." at 6241.64,-1058.36 h45
  text ".print_Scale" at 11261.14,-1059.19 h70
  text ".Application_BuildNumber" at 12766.64,-1059.19 h70
  text "1" at 607.48,-1265.86 h70
  text "2" at 3103.14,-1265.86 h70
  text "3" at 5592.48,-1265.86 h70
  text "4" at 8099.15,-1265.86 h70
  text "5" at 10598.14,-1265.86 h70
  text "6" at 13103.14,-1265.86 h70
M10 Fab Notes:
  drawing of 212 lines, arcs and shapes, not listed
  text "DESIGN INFORMATION" at 12248.66,6807.64 h60
  text "(REFER ALSO ARRAY/PANEL PROFILING INFORMATION)" at 11887.1,6645.92 h60
  text "BOARD SIZE" at 11201.1,6641.64 h60
  text "795.28MIL" at 11663.42,6513.82 h60
  text "X" at 12169.1,6513.82 h60
  text "795.28MIL" at 12400.42,6513.82 h60
  text "Number of Layers :" at 11604.1,6316.64 h60
  text "6" at 12698.91,6306.64 h60
  text "MIN. TRACK WIDTH:" at 11604.1,6177.64 h60
  text "5" at 12700.34,6177.64 h60
  text "MIL" at 12855.1,6177.64 h60
  text "MIN. CLEARANCE:" at 11604.1,6045.64 h60
  text "4" at 12700.34,6045.64 h60
  text "MIL" at 12855.1,6045.64 h60
  text "MIN. VIA PAD SIZE:" at 11604.1,5913.64 h60
  text "10" at 12670.35,5913.64 h60
  text "MIL" at 12855.1,5913.64 h60
  text "0.05mm (2MIL)" at 12299.1,5771.93 h60
  text "MINIMUM ANNULAR RING" at 11274.87,5767.64 h60
  text "EXTERNAL" at 13007.1,5767.64 h60
  text "PER" at 11474.87,5649.64 h60
  text "IPC-D-275 CLASS 2 LEVEL C" at 11694.87,5649.64 h60
  text "MIL, HOLES" at 13183.1,5537.35 h60
  text "+/-" at 12790.64,5536.64 h60
  text "+/-" at 13644.64,5536.64 h60
  text "REGISTRATION TOLERANCES:" at 11274.87,5531.64 h60
  text "METAL" at 12474.64,5531.64 h60
  text "5" at 13050.84,5531.64 h60
  text "3" at 13883.84,5531.64 h60
  text "MIL" at 14000.1,5531.64 h60
  text "MATERIAL:" at 11200.1,5322.18 h60
  text "FR-4 High Tg" at 12186.54,5181.85 h60
  text "FR-408" at 11621.1,5173.28 h60
  text "X" at 12033.1,5173.28 h60
  text "OTHER" at 13109.1,5173.28 h60
  text "62 MIL (1.6mm) +/-10%" at 11941.2,5010.56 h60
  text "THICKNESS:" at 11274.87,5006.28 h60
  text "X" at 11813.04,5006.28 h60
  text "OTHER" at 13226.1,5006.28 h60
  text "TOLERANCE:" at 11274.87,4848.28 h60
  text "X" at 12114.17,4848.28 h60
  text "ANSI IPC-6012 TYPE 3 CLASS 2" at 12301.11,4848.28 h60
  text "OTHER +/-" at 12301.1,4692.28 h60
  text "BOW & TWIST:" at 11274.87,4535.28 h60
  text "X" at 12114.17,4535.28 h60
  text "ANSI IPC-6012 TYPE 3 CLASS 2" at 12301.11,4535.28 h60
  text "OTHER +/-" at 12301.1,4376.77 h60
  text "COPPER THICKNESS (FINISHED):" at 11200.1,4241.28 h60
  text "1.4MIL (1oz)" at 12080.1,4088.56 h60
  text "2MIL (1.4oz)" at 12847.1,4088.56 h60
  text "2.8MIL (2oz)" at 13574.1,4088.56 h60
  text "OUTER:" at 11557.1,4084.28 h60
  text "X" at 11951.64,4083.64 h60
  text "1.4MIL (1oz)" at 12080.1,3931.56 h60
  text "2.8MIL (2oz)" at 12847.1,3931.56 h60
  text "N/A" at 13573.64,3931.92 h60
  text "INNER SIGNAL:" at 11268.02,3927.28 h60
  text "X" at 11953.06,3927.28 h60
  text "DRILLING:" at 11200.1,3788.28 h60
  text "REFERENCE:" at 11274.87,3671.28 h60
  text "X" at 11923.1,3671.28 h60
  text "AS SHOWN" at 12110.1,3671.28 h60
  text "X" at 12824.1,3671.28 h60
  text "NC_DRILL FILES" at 12961.1,3671.28 h60
  text "PTH MIN COPPER THICKNESS:" at 11274.87,3513.28 h60
  text "X" at 12625.1,3513.28 h60
  text "1MIL" at 12762.1,3513.28 h60
  text "OTHER" at 13259.1,3513.28 h60
  text "BOARD FINISH:" at 11200.1,3354.28 h60
  text "SILKSCREEN:" at 11355.32,3236.28 h60
  text "X" at 12304.1,3236.28 h60
  text "TOP" at 12430.1,3236.28 h60
  text "X" at 12814.1,3236.28 h60
  text "BOTTOM" at 12941.1,3236.28 h60
  text "SILKSCREEN COLOR:" at 11355.32,3069.28 h60
  text "X" at 12303.06,3069.28 h60
  text "WHITE" at 12430.1,3069.28 h60
  text "OTHER" at 12941.1,3069.28 h60
  text "SOLDER RESIST COLOR:" at 11355.32,2899.28 h60
  text "GREEN" at 12050.1,2740.08 h60
  text "BLUE" at 12641.1,2740.08 h60
  text "OTHER" at 13179.1,2740.08 h60
  text "BLACK" at 13661.1,2740.08 h60
  text "X" at 13027.64,2737.64 h60
  text "IMMERSION GOLD (ENIG)" at 12261.1,2551.56 h60
  text "ENEPIG" at 13598.64,2548.28 h60
  text "SURFACE FINISH:" at 11200.1,2547.28 h60
  text "X" at 12074.15,2547.28 h60
  text "IMM. TIN/SILVER OR EQUIV" at 11529.64,2390.28 h60
  text "OTHER" at 12961.1,2390.28 h60
  text "ARRAY/PANEL:" at 11200.1,2211.28 h60
  text "CUT AND TRIM PER MECH LAYER 1" at 12261.1,2206.99 h60
  text "N.C. ROUTE" at 12261.1,2055.28 h60
  text "X" at 12940.1,2055.28 h60
  text "V. SCORE" at 13127.1,2055.28 h60
  text "CERTIFICATION:" at 11200.1,1918.28 h60
  text "MATERIALS AND WORKMANSHIP FOR ALL PCBS" at 11925.1,1918.28 h60
  text "TO MEET OR EXCEED THE REQUIREMENTS OF:" at 11925.1,1820.28 h60
  text "X" at 11551.6,1683.77 h60
  text "ANSI IPC-A-600F CLASS ->" at 11690.6,1683.77 h60
  text "X" at 13329.66,1683.77 h60
  text "2" at 13448.6,1683.77 h60
  text "1" at 13133.6,1682.28 h60
  text "3" at 13802.6,1682.28 h60
  text "X" at 11553.66,1524.28 h60
  text "UL 94V-0" at 11690.6,1524.28 h60
  text "X" at 12365.66,1524.28 h60
  text "RoHS" at 12502.6,1524.28 h60
  text "OTHER" at 13147,1524.28 h60
  text "PER ORDER" at 13544.06,1524.28 h60
  text "ADDITIONAL REQUIREMENTS:" at 11200.1,1383.28 h60
  text "MICROSECTION:" at 11274.87,1268.28 h60
  text "YES" at 12180.6,1268.28 h60
  text "REQUIRED" at 13042.1,1112.13 h60
  text "BARE BOARD ELEC. TEST:" at 11274.87,1109.28 h60
  text "NONE" at 12580.6,1109.28 h60
  text "X" at 12915.1,1109.28 h60
  text "PER ORDER" at 13634.1,1109.28 h60
  text "MANUFACTURER'S UL:" at 11274.87,952.28 h60
  text "RAIL" at 12440.6,947.99 h60
  text "METAL" at 12932.41,947.99 h60
  text "X" at 13307.64,947.64 h60
  text "SILK" at 13444.1,947.99 h60
  text ".Layer_Name" at 444.64,-860.86 h60
M11 Gerber Information:
  lines w10: -424.36,-932.53 6175.64,-932.53 ; -424.36,-729.2 6177.64,-729.2 ; -424.36,-525.86 -424.36,-1135.86 3580.64,-1135.86 6177.64,-1135.86 6177.64,-525.86 -423.86,-525.86 -423.86,-1135.86 1151.64,-1135.86 ; 2040.64,-1135.86 2040.64,-525.86 ; 3307.64,-729.2 3307.64,-525.86 ; 4147.64,-729.2 4147.64,-525.86 ; 4769.64,-1142.36 4769.64,-939.53
  text "ALL ARTWORK VIEWED FROM TOP SIDE" at -360.86,-658.03 h60
  text "BOARD #:" at 2115.64,-658.03 h60
  text ".PRJ_Number" at 2661.14,-658.03 h60
  text "REV:" at 3505.64,-658.03 h60
  text ".PCB_Rev" at 3797.14,-658.03 h60
  text "SVN REV:" at 4343.64,-658.03 h60
  text ".VersionControl_RevNumber" at 4849.64,-658.03 h60
  text "LAYER NAME =" at -360.86,-860.86 h60
  text "PLOT NAME =" at -360.86,-1066.7 h60
  text ".plot_File_Name" at 444.64,-1066.7 h60
  text "GENERATED    :" at 2117.64,-1066.7 h60
  text ".Print_Date" at 2987.14,-1066.7 h60
  text ".Print_Time" at 3716.14,-1066.7 h60
  text "TEXAS INSTRUMENTS" at 4980.64,-1066.7 h60
M12 Stackup:
  drawing of 399 lines, arcs and shapes, not listed
  text "Layer" at 6186.14,7818.14 h60
  text "Name" at 6596.05,7818.14 h60
  text "Material" at 8005.64,7818.14 h60
  text "Thickness" at 8865.41,7818.14 h60
  text "Constant" at 9515.24,7818.14 h60
  text "Board Layer Stack" at 10085.1,7818.14 h60
  text "1" at 6186.14,7698.14 h60
  text "Top Overlay" at 6596.05,7698.14 h60
  text "2" at 6186.14,7578.14 h60
  text "Top Solder" at 6596.05,7578.14 h60
  text "Solder Resist" at 8005.64,7578.14 h60
  text "0.40mil" at 8865.41,7578.14 h60
  text "3.5" at 9515.24,7578.14 h60
  text "3" at 6186.14,7458.14 h60
  text "Layer 1 - Top Layer" at 6596.05,7458.14 h60
  text "Copper" at 8005.64,7458.14 h60
  text "1.40mil" at 8865.41,7458.14 h60
  text "4" at 6186.14,7338.14 h60
  text "Dielectric 1" at 6596.05,7338.14 h60
  text "370HR" at 8005.64,7338.14 h60
  text "12.60mil" at 8865.41,7338.14 h60
  text "4.2" at 9515.24,7338.14 h60
  text "5" at 6186.14,7218.14 h60
  text "Layer 2 - GND" at 6596.05,7218.14 h60
  text "Copper" at 8005.64,7218.14 h60
  text "1.40mil" at 8865.41,7218.14 h60
  text "6" at 6186.14,7098.14 h60
  text "Dielectric 2" at 6596.05,7098.14 h60
  text "370HR" at 8005.64,7098.14 h60
  text "8.00mil" at 8865.41,7098.14 h60
  text "4.2" at 9515.24,7098.14 h60
  text "7" at 6186.14,6978.14 h60
  text "Layer 3 - PWR" at 6596.05,6978.14 h60
  text "Copper" at 8005.64,6978.14 h60
  text "1.40mil" at 8865.41,6978.14 h60
  text "8" at 6186.14,6858.14 h60
  text "Dielectric 5" at 6596.05,6858.14 h60
  text "370HR" at 8005.64,6858.14 h60
  text "12.60mil" at 8865.41,6858.14 h60
  text "4.2" at 9515.24,6858.14 h60
  text "9" at 6186.14,6738.14 h60
  text "Layer 4 - Signal" at 6596.05,6738.14 h60
  text "Copper" at 8005.64,6738.14 h60
  text "1.40mil" at 8865.41,6738.14 h60
  text "10" at 6186.14,6618.14 h60
  text "Dielectric 4" at 6596.05,6618.14 h60
  text "370HR" at 8005.64,6618.14 h60
  text "8.00mil" at 8865.41,6618.14 h60
  text "4.2" at 9515.24,6618.14 h60
  text "11" at 6186.14,6498.14 h60
  text "Layer 5 - Signal/Gnd" at 6596.05,6498.14 h60
  text "Copper" at 8005.64,6498.14 h60
  text "1.40mil" at 8865.41,6498.14 h60
  text "12" at 6186.14,6378.14 h60
  text "Dielectric 3" at 6596.05,6378.14 h60
  text "370HR" at 8005.64,6378.14 h60
  text "12.60mil" at 8865.41,6378.14 h60
  text "4.2" at 9515.24,6378.14 h60
  text "13" at 6186.14,6258.14 h60
  text "Layer 6 - Bottom Layer" at 6596.05,6258.14 h60
  text "Copper" at 8005.64,6258.14 h60
  text "1.40mil" at 8865.41,6258.14 h60
  text "14" at 6186.14,6138.14 h60
  text "Bottom Solder" at 6596.05,6138.14 h60
  text "Solder Resist" at 8005.64,6138.14 h60
  text "0.40mil" at 8865.41,6138.14 h60
  text "3.5" at 9515.24,6138.14 h60
  text "15" at 6186.14,6018.14 h60
  text "Bottom Overlay" at 6596.05,6018.14 h60
  text ".Layer_Name" at 444.64,-860.86 h60
M13 Component Bodies Top:
  text ".Layer_Name" at 444.64,-860.86 h60
M14 Component Bodies Bottom:
  text ".Layer_Name" at 444.64,-860.86 h60
M15 Courtyards Top:
  text ".Layer_Name" at 444.64,-860.86 h60
M16 Courtyards Bottom:
  text ".Layer_Name" at 444.64,-860.86 h60
Drill Drawing:
  circle w10: c1451.36,218.68 r16.58
  circle w10: c1451.36,218.68 r27.63
  lines w10: 1423.73,315.37 1478.98,315.37 1478.98,370.63 1423.73,370.63 1423.73,315.37 ; 1423.73,453.51 1437.54,453.51 1451.36,439.69 1465.17,453.51 1478.98,453.51 1465.17,467.32 1478.98,481.13 1465.17,481.13 1451.36,494.95 1437.54,481.13 1423.73,481.13 1437.54,467.32 1423.73,453.51 ; 1423.73,564.01 1478.98,564.01 1478.98,619.27 1423.73,619.27 1423.73,564.01 ; 1423.73,702.15 1437.54,702.15 1437.54,688.33 1465.17,688.33 1465.17,702.15 1478.98,702.15 1478.98,729.77 1465.17,729.77 1465.17,743.59 1437.54,743.59 1437.54,729.77 1423.73,729.77 1423.73,702.15 ; 1423.73,812.65 1451.36,826.47 1478.98,812.65 1465.17,840.28 1478.98,867.91 1451.36,854.09 1423.73,867.91 1437.54,840.28 1423.73,812.65 ; 1423.73,964.6 1451.36,936.97 1478.98,964.6 1451.36,992.23 1423.73,964.6 ; 1423.73,1116.55 1478.98,1116.55 1451.36,1061.29 1423.73,1116.55 ; 1434.78,326.42 1467.93,326.42 1467.93,359.58 1434.78,359.58 1434.78,326.42 ; 1434.78,459.03 1443.07,459.03 1451.36,450.74 1459.64,459.03 1467.93,459.03 1459.64,467.32 1467.93,475.61 1459.64,475.61 1451.36,483.9 1443.07,475.61 1434.78,475.61 1443.07,467.32 1434.78,459.03 ; 1434.78,707.67 1443.07,707.67 1443.07,699.38 1459.64,699.38 1459.64,707.67 1467.93,707.67 1467.93,724.25 1459.64,724.25 1459.64,732.54 1443.07,732.54 1443.07,724.25 1434.78,724.25 1434.78,707.67 ; 1434.78,823.7 1451.36,831.99 1467.93,823.7 1459.64,840.28 1467.93,856.86 1451.36,848.57 1434.78,856.86 1443.07,840.28 1434.78,823.7 ; 1434.78,1105.5 1467.93,1105.5 1451.36,1072.34 1434.78,1105.5
  lines w12: 1373.64,153.76 5073.77,153.76 ; 1373.64,1148.32 5073.77,1148.32 ; 1711.5,29.44 1711.5,1272.64 ; 2043.5,29.44 2043.5,1272.64 ; 2680.06,29.44 2680.06,1272.64 ; 2939.2,29.44 2939.2,1272.64 ; 3314.36,29.44 3314.36,1272.64 ; 4507.33,29.44 4507.33,1272.64 ; 1373.64,29.44 5073.77,29.44 5073.77,1272.64 1373.64,1272.64 1373.64,29.44
  text "Symbol" at 1448.23,1185.61 h72
  text "Quantity" at 1748.8,1185.61 h72
  text "Finished Hole Size" at 2080.8,1185.61 h72
  text "Plated" at 2717.36,1185.61 h72
  text "Hole Type" at 2976.5,1185.61 h72
  text "Drill Layer Pair" at 3351.66,1185.61 h72
  text "Hole Tolerance" at 4544.63,1185.61 h72
  text "2" at 1748.8,1061.29 h60
  text "62.99mil (1.600mm)" at 2080.8,1061.29 h60
  text "NPTH" at 2717.36,1061.29 h60
  text "Round" at 2976.5,1061.29 h60
  text "Layer 1 - Top Layer - Layer 6 - Bottom Layer" at 3351.66,1061.29 h60
  text "1" at 1748.8,936.97 h60
  text "280.00mil (7.112mm)" at 2080.8,936.97 h60
  text "NPTH" at 2717.36,936.97 h60
  text "Round" at 2976.5,936.97 h60
  text "Layer 1 - Top Layer - Layer 6 - Bottom Layer" at 3351.66,936.97 h60
  text "89" at 1748.8,812.65 h60
  text "6.00mil (0.152mm)" at 2080.8,812.65 h60
  text "PTH" at 2717.36,812.65 h60
  text "Round" at 2976.5,812.65 h60
  text "Layer 1 - Top Layer - Layer 6 - Bottom Layer" at 3351.66,812.65 h60
  text "16" at 1748.8,688.33 h60
  text "7.87mil (0.200mm)" at 2080.8,688.33 h60
  text "PTH" at 2717.36,688.33 h60
  text "Round" at 2976.5,688.33 h60
  text "Layer 1 - Top Layer - Layer 6 - Bottom Layer" at 3351.66,688.33 h60
  text "6" at 1748.8,564.01 h60
  text "8.00mil (0.203mm)" at 2080.8,564.01 h60
  text "PTH" at 2717.36,564.01 h60
  text "Round" at 2976.5,564.01 h60
  text "Layer 1 - Top Layer - Layer 6 - Bottom Layer" at 3351.66,564.01 h60
  text "26" at 1748.8,439.69 h60
  text "10.00mil (0.254mm)" at 2080.8,439.69 h60
  text "PTH" at 2717.36,439.69 h60
  text "Round" at 2976.5,439.69 h60
  text "Layer 1 - Top Layer - Layer 6 - Bottom Layer" at 3351.66,439.69 h60
  text "1" at 1748.8,315.37 h60
  text "35.43mil (0.900mm)" at 2080.8,315.37 h60
  text "PTH" at 2717.36,315.37 h60
  text "Round" at 2976.5,315.37 h60
  text "Layer 1 - Top Layer - Layer 6 - Bottom Layer" at 3351.66,315.37 h60
  text "4" at 1748.8,191.05 h60
  text "55.12mil (1.400mm)" at 2080.8,191.05 h60
  text "PTH" at 2717.36,191.05 h60
  text "Round" at 2976.5,191.05 h60
  text "Layer 1 - Top Layer - Layer 6 - Bottom Layer" at 3351.66,191.05 h60
  text "145 Total" at 1748.8,66.73 h60
  text ".Layer_Name" at 444.64,-860.86 h60
Mechanical 17:
  circle w10: c397.64,397.64 r240.16
  circle w10: c397.64,397.64 r236.22
  lines w10: 43.31,303.15 7.87,303.15 cw(c7.87,397.64) 7.87,492.13 43.31,492.13 ; 751.97,303.15 789.35,303.15 ccw(c789.35,397.64) 789.35,492.13 751.97,492.13 ; 43.31,43.31 751.97,43.31 751.97,751.97 43.31,751.97 43.31,43.31 ; 82.68,82.68 82.68,712.6 712.6,712.6 712.6,82.68 82.68,82.68

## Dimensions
0,795.28 to 0,0 on M2 Board Dimensions
0,0 to 795.28,0 on M2 Board Dimensions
